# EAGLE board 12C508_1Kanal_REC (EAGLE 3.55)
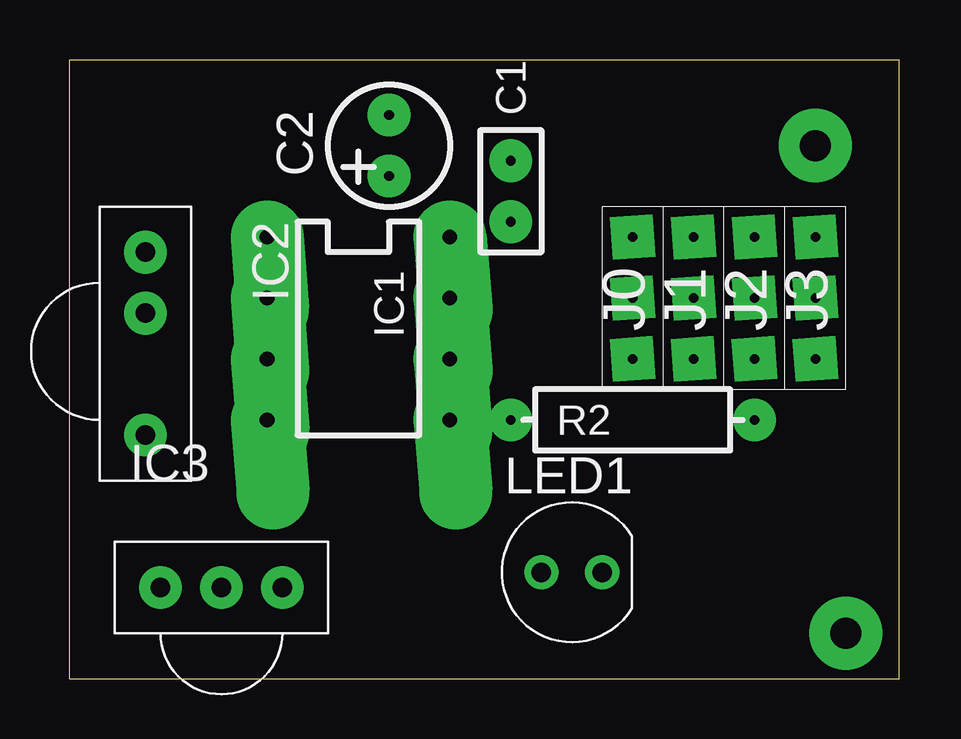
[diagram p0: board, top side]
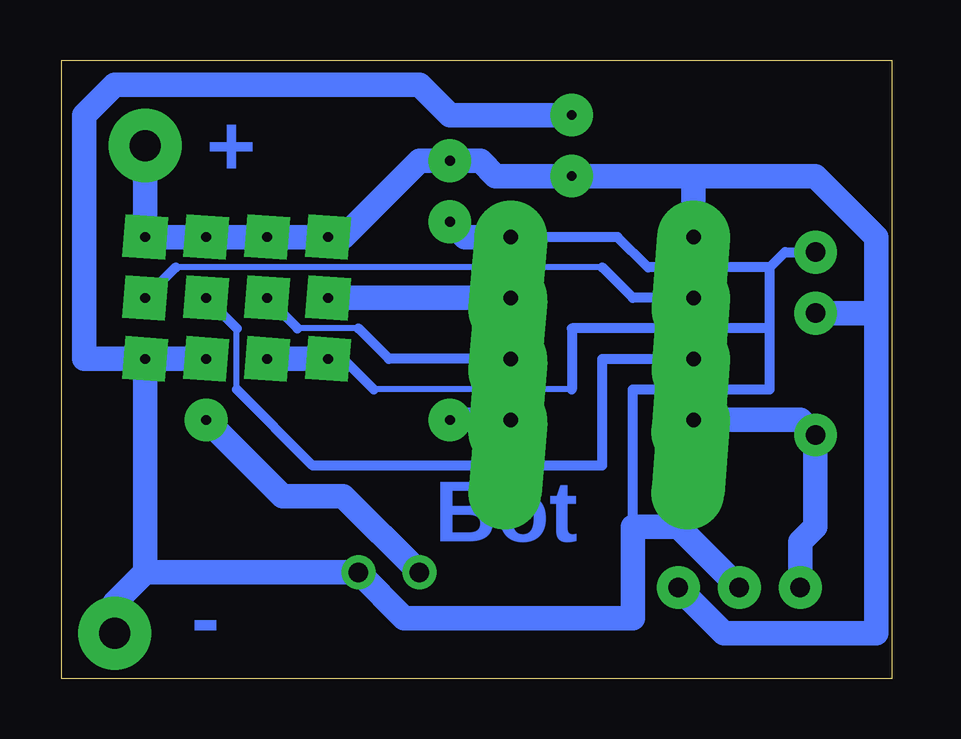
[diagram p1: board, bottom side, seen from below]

Size 34.6 x 25.79 mm. Coordinates in mm from the lower left corner, seen from the top.
Outline: 0,0 34.6,0 34.6,25.79 0,25.79 0,0
Copper layers used: Bottom

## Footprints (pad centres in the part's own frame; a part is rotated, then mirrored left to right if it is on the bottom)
RM2,5 = drill 0.406 pad 1.778 round:  0,0;  2.54,0
KO01 = drill 0.406 pad 1.778 round:  0,0;  2.54,0
L-8B = drill 0.61 pad 3.048 offset:  0,0;  2.54,0;  5.08,0;  7.62,0;  7.62,7.62;  5.08,7.62;  2.54,7.62;  0,7.62
OP1736 = drill 0.813 pad 1.778 round:  0,0;  2.54,0;  7.62,0
OP1836 = drill 0.813 pad 1.778 round:  0,0;  2.54,0;  5.08,0
MPER_3 = drill 0.406 pad 1.778 square:  0,0;  2.54,0;  5.08,0
D_5MM = drill 0.813 pad 1.422 round:  -1.27,0;  1.27,0
GEL = drill 1.295 pad 3.048 round:  0,0
S04 = drill 0.406 pad 1.778 round:  0,0;  10.16,0

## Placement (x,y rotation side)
C1  C100NK  [RM2,5]  18.41,19.05 90 top
C2  100u  [KO01]  13.34,20.95 90 top
IC1  12C508P  [L-8B]  8.26,18.41 270 top
IC2  TSOP1736  [OP1736]  3.17,17.78 270 top
IC3  TSOP1836  [OP1836]  3.81,3.81 0 top
J0  JUMPER_3  [MPER_3]  23.5,18.41 270 top
J1  JUMPER_3  [MPER_3]  26.04,18.41 270 top
J2  JUMPER_3  [MPER_3]  28.57,18.41 270 top
J3  JUMPER_3  [MPER_3]  31.11,18.41 270 top
LED1  REC  [D_5MM]  20.95,4.45 0 top
N1  +  [GEL]  31.11,22.23 0 top
N2  -  [GEL]  32.38,1.91 0 top
R2  270  [S04]  18.41,10.79 0 top

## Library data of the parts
C1 C2 IC1 J0 J1-J3 R2 = holg_plt
IC2 IC3 = ic_holg
LED1 N1 N2 = holgnorm

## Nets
+5V: C1. C2. IC1. IC2. IC3. J0. J1. J2. J3. N1.
GND: C1. C2. IC1. IC2. IC3. J0. J1. J2. J3. LED1. N2.
N$2: LED1. R2.
N$3: IC1. IC2. IC3.
N$6: IC1. R2.
N$11: IC1. J0.
N$13: IC1. J1.
N$17: IC1. J2.
N$18: IC1. J3.

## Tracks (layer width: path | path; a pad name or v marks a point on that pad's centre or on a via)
+5V
  Bottom 0.406: 22.86,18.41 23.5,18.41
  Bottom 1.016: 8.26,20.95 13.34,20.95 16.51,20.95 17.14,21.59 C1. 19.68,21.59 22.86,18.41 | 23.5,18.41 26.04,18.41 28.57,18.41 31.11,18.41 N1. | 8.26,20.95 8.26,18.41 | 8.26,20.95 3.17,20.95 0.64,18.41 0.64,15.24 | 0.64,15.24 3.17,15.24 | IC3. 6.99,1.91 0.64,1.91 0.64,15.24
GND
  Bottom 0.254: 13.34,12.06 21.59,12.06
  Bottom 0.406: J1. J0. 22.86,13.34 21.59,12.06 | 13.34,12.06 13.34,14.61 5.08,14.61 | IC1. 11.43,18.41 10.16,17.14 5.08,17.14 | 5.08,17.14 4.45,17.78 3.17,17.78 | 5.08,14.61 5.08,17.14 | 5.08,14.61 5.08,12.06 10.79,12.06 10.79,6.35
  Bottom 1.016: J3. 33.66,13.34 33.66,23.5 32.38,24.77 19.68,24.77 18.41,23.5 C2. | J3. J2. | J0. J1. | 31.11,4.45 J3. | 6.35,3.81 8.89,6.35 10.79,6.35 10.79,2.54 20.32,2.54 LED1. 31.11,4.45 | N2. 32.38,3.17 31.11,4.45 | 18.41,19.05 17.78,18.41 IC1.
N$2
  Bottom 1.016: R2. 25.4,7.62 22.86,7.62 19.68,4.45
N$3
  Bottom 1.016: 8.26,10.79 3.81,10.79 IC2. 3.17,6.35 3.81,5.71 3.81,3.81
N$6
  Bottom 1.016: 15.88,10.79 18.41,10.79
N$11
  Bottom 1.016: 15.88,15.88 23.5,15.88
N$13
  Bottom 0.254: 22.23,14.61 24.77,14.61
  Bottom 0.406: 15.88,13.34 20.95,13.34 22.23,14.61 | 24.77,14.61 26.04,15.88
N$17
  Bottom 0.254: 27.3,12.06 27.3,14.61
  Bottom 0.406: 8.26,13.34 12.06,13.34 12.06,8.89 24.13,8.89 27.3,12.06 | 27.3,14.61 28.57,15.88
N$18
  Bottom 0.254: 12.06,17.14 29.84,17.14
  Bottom 0.406: 8.26,15.88 10.79,15.88 12.06,17.14 | 29.84,17.14 31.11,15.88

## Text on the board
Bottom: + | Bot | -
